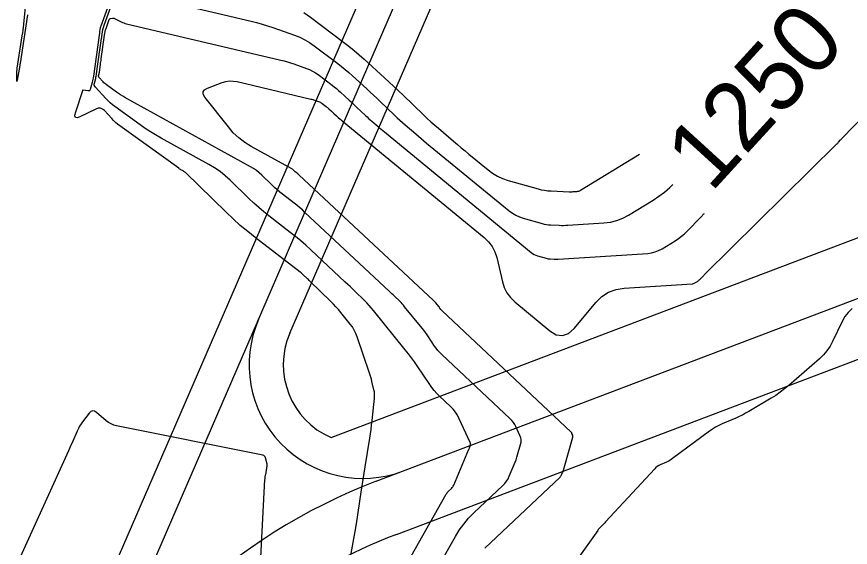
# Model space of a CAD drawing. Extents: x 658976 to 668726, y 639543 to 647196.
# Drawn here: x 661532.6 to 661605.9, y 641588.4 to 641635 of the extents above; entities that cross this region are included whole.
import ezdxf

# ---------------------------------------------------------------- set-up
doc = ezdxf.new("R2010")
doc.units = 0
for name, color, linetype in [('Ex_Contour Labels', 7, 'Continuous'), ('Ex_Major Contours', 7, 'Continuous'), ('Ex_Minor Contours', 7, 'Continuous'), ('R_Water', 7, 'Continuous')]:
    doc.layers.add(name, color=color, linetype=linetype)

msp = doc.modelspace()

# ---------------------------------------------------------------- linework, layer by layer
at = {"layer": 'Ex_Major Contours'}
for points in [[(661566.923, 641586.907), (661570.37, 641593.022), (661570.416, 641593.096), (661570.467, 641593.167), (661570.523, 641593.234), (661570.584, 641593.296), (661570.84, 641593.538), (661570.901, 641593.602), (661570.954, 641593.67), (661570.999, 641593.743), (661571.037, 641593.822), (661572.37, 641596.981), (661572.389, 641597.029), (661572.407, 641597.076), (661572.423, 641597.124), (661572.437, 641597.173), (661572.493, 641597.369), (661572.503, 641597.417), (661572.504, 641597.465), (661572.496, 641597.512), (661572.479, 641597.559), (661571.526, 641599.667), (661571.374, 641599.963), (661571.196, 641600.239), (661570.992, 641600.497), (661570.761, 641600.736), (661569.786, 641601.653), (661569.549, 641601.889), (661569.326, 641602.137), (661569.118, 641602.396), (661568.925, 641602.669), (661567.826, 641604.308), (661567.577, 641604.671), (661567.32, 641605.028), (661567.055, 641605.379), (661566.782, 641605.724), (661563.982, 641609.181), (661563.794, 641609.406), (661563.6, 641609.625), (661563.4, 641609.839), (661563.194, 641610.046), (661562.357, 641610.866), (661562.147, 641611.071), (661561.936, 641611.274), (661561.723, 641611.476), (661561.51, 641611.677), (661558.468, 641614.525), (661558.034, 641614.922), (661557.591, 641615.308), (661557.138, 641615.683), (661556.677, 641616.047), (661554.802, 641617.492), (661554.347, 641617.853), (661553.903, 641618.228), (661553.47, 641618.615), (661553.048, 641619.015), (661551.384, 641620.641), (661550.957, 641621.032), (661550.506, 641621.392), (661550.032, 641621.72), (661549.534, 641622.017), (661545.322, 641624.342), (661544.851, 641624.612), (661544.388, 641624.896), (661543.934, 641625.194), (661543.489, 641625.505), (661541.272, 641627.108), (661541.063, 641627.267), (661540.862, 641627.436), (661540.67, 641627.615), (661540.487, 641627.804), (661539.557, 641628.812), (661539.498, 641628.893), (661539.464, 641628.98), (661539.454, 641629.073), (661539.47, 641629.172), (661539.583, 641629.581), (661539.609, 641629.683), (661539.633, 641629.787), (661539.652, 641629.891), (661539.669, 641629.995), (661539.93, 641631.88), (661539.957, 641632.081), (661539.985, 641632.281), (661540.013, 641632.482), (661540.04, 641632.682), (661540.15, 641633.484), (661540.182, 641633.684), (661540.225, 641633.88), (661540.278, 641634.074), (661540.341, 641634.266), (661541.478, 641637.437)], [(661546.512, 641636.195), (661553.231, 641634.61), (661553.717, 641634.489), (661554.199, 641634.355), (661554.677, 641634.208), (661555.152, 641634.048), (661557.043, 641633.385), (661557.506, 641633.202), (661557.952, 641632.986), (661558.379, 641632.735), (661558.788, 641632.45), (661560.852, 641630.892), (661561.183, 641630.636), (661561.507, 641630.372), (661561.825, 641630.1), (661562.136, 641629.82), (661563.397, 641628.659), (661563.69, 641628.389), (661563.981, 641628.117), (661564.271, 641627.843), (661564.559, 641627.568), (661565.838, 641626.345), (661566.064, 641626.132), (661566.293, 641625.921), (661566.524, 641625.714), (661566.759, 641625.51), (661567.704, 641624.701), (661567.94, 641624.499), (661568.178, 641624.299), (661568.417, 641624.099), (661568.656, 641623.901), (661575.914, 641617.934), (661576.194, 641617.726), (661576.491, 641617.55), (661576.805, 641617.406), (661577.136, 641617.294), (661578.804, 641616.819), (661578.987, 641616.772), (661579.173, 641616.737), (661579.36, 641616.713), (661579.549, 641616.7), (661580.309, 641616.669), (661580.499, 641616.664), (661580.689, 641616.664), (661580.879, 641616.668), (661581.068, 641616.678), (661584.217, 641616.878), (661584.794, 641616.949), (661585.35, 641617.088), (661585.884, 641617.295), (661586.397, 641617.569), (661588.544, 641618.886), (661589.057, 641619.223), (661589.546, 641619.59), (661590.01, 641619.988), (661590.284, 641620.253)]]:
    msp.add_lwpolyline(points, dxfattribs=at)
at = {"layer": 'Ex_Minor Contours'}
for points in [[(661562.032, 641587.812), (661562.156, 641588.459), (661562.273, 641589.108), (661562.381, 641589.758), (661562.482, 641590.409), (661562.9, 641593.216), (661562.983, 641593.768), (661563.068, 641594.319), (661563.155, 641594.87), (661563.244, 641595.421), (661563.656, 641597.947), (661563.717, 641598.336), (661563.772, 641598.725), (661563.822, 641599.115), (661563.866, 641599.506), (661564.075, 641601.48), (661564.086, 641601.665), (661564.082, 641601.85), (661564.061, 641602.034), (661564.025, 641602.216), (661563.845, 641602.944), (661563.798, 641603.126), (661563.748, 641603.306), (661563.694, 641603.485), (661563.636, 641603.664), (661562.557, 641606.863), (661562.44, 641607.166), (661562.297, 641607.454), (661562.13, 641607.729), (661561.937, 641607.99), (661561.114, 641609.005), (661560.905, 641609.256), (661560.689, 641609.5), (661560.466, 641609.738), (661560.236, 641609.97), (661558.405, 641611.763), (661558.336, 641611.83), (661558.267, 641611.896), (661558.198, 641611.962), (661558.129, 641612.028), (661557.85, 641612.289), (661557.779, 641612.353), (661557.707, 641612.416), (661557.634, 641612.477), (661557.559, 641612.536), (661553.6, 641615.586), (661552.934, 641616.115), (661552.284, 641616.663), (661551.65, 641617.23), (661551.033, 641617.816), (661547.462, 641621.307), (661547.419, 641621.346), (661547.375, 641621.381), (661547.327, 641621.414), (661547.278, 641621.444), (661547.076, 641621.555), (661547.026, 641621.584), (661546.977, 641621.614), (661546.928, 641621.646), (661546.881, 641621.679), (661541.7, 641625.424), (661541.511, 641625.568), (661541.329, 641625.721), (661541.156, 641625.883), (661540.991, 641626.053), (661540.345, 641626.753), (661540.177, 641626.893), (661539.996, 641626.963), (661539.802, 641626.962), (661539.595, 641626.892), (661538.204, 641626.204), (661537.952, 641626.113), (661537.802, 641626.14), (661537.755, 641626.284), (661537.81, 641626.546), (661538.46, 641628.513), (661538.462, 641628.52), (661538.463, 641628.528), (661538.463, 641628.535), (661538.462, 641628.543), (661538.456, 641628.574), (661538.455, 641628.581), (661538.457, 641628.585), (661538.461, 641628.587), (661538.468, 641628.587), (661538.936, 641628.514), (661539.009, 641628.512), (661539.068, 641628.534), (661539.111, 641628.578), (661539.14, 641628.645), (661539.308, 641629.252), (661539.341, 641629.379), (661539.37, 641629.508), (661539.394, 641629.637), (661539.415, 641629.768), (661539.914, 641633.375), (661539.924, 641633.444), (661539.934, 641633.514), (661539.943, 641633.584), (661539.953, 641633.653), (661539.991, 641633.932), (661540.002, 641634.002), (661540.017, 641634.07), (661540.035, 641634.137), (661540.057, 641634.204), (661541.343, 641637.791)], [(661533.607, 641635.163), (661532.941, 641630.892), (661532.936, 641630.861), (661532.931, 641630.83), (661532.923, 641630.769), (661532.92, 641630.754), (661532.918, 641630.738), (661532.915, 641630.723), (661532.913, 641630.708), (661532.856, 641630.39), (661532.686, 641629.43), (661532.666, 641629.332), (661532.652, 641629.3), (661532.644, 641629.334), (661532.642, 641629.434), (661532.648, 641629.968), (661532.652, 641630.101), (661532.66, 641630.233), (661532.674, 641630.366), (661532.692, 641630.498), (661533.133, 641633.32), (661533.172, 641633.578), (661533.207, 641633.838), (661533.24, 641634.097), (661533.269, 641634.357), (661533.427, 641635.837)], [(661557.871, 641635.384), (661558.448, 641634.982), (661561.359, 641632.784), (661561.826, 641632.423), (661562.283, 641632.051), (661562.731, 641631.668), (661563.17, 641631.273), (661564.949, 641629.636), (661565.362, 641629.254), (661565.772, 641628.871), (661566.181, 641628.485), (661566.588, 641628.097), (661568.391, 641626.372), (661568.71, 641626.071), (661569.033, 641625.774), (661569.36, 641625.482), (661569.691, 641625.195), (661571.023, 641624.053), (661571.356, 641623.769), (661571.692, 641623.486), (661572.028, 641623.205), (661572.366, 641622.925), (661574.045, 641621.545), (661574.449, 641621.245), (661574.878, 641620.992), (661575.331, 641620.783), (661575.808, 641620.621), (661578.439, 641619.872), (661578.722, 641619.801), (661579.008, 641619.746), (661579.296, 641619.709), (661579.587, 641619.689), (661581.167, 641619.625), (661581.253, 641619.623), (661581.34, 641619.623), (661581.427, 641619.625), (661581.514, 641619.629), (661581.861, 641619.651), (661581.946, 641619.662), (661582.028, 641619.682), (661582.107, 641619.713), (661582.182, 641619.753), (661587.356, 641622.926)], [(661569.757, 641586.783), (661571.178, 641589.304), (661571.525, 641589.869), (661571.912, 641590.404), (661572.337, 641590.908), (661572.802, 641591.381), (661575.337, 641593.78), (661575.515, 641593.966), (661575.671, 641594.167), (661575.805, 641594.384), (661575.917, 641594.616), (661576.345, 641595.632), (661576.431, 641595.843), (661576.509, 641596.056), (661576.582, 641596.271), (661576.647, 641596.489), (661576.905, 641597.389), (661576.945, 641597.593), (661576.949, 641597.795), (661576.916, 641597.995), (661576.846, 641598.191), (661576.493, 641598.972), (661576.396, 641599.162), (661576.282, 641599.339), (661576.151, 641599.504), (661576.004, 641599.657), (661569.977, 641605.322), (661569.807, 641605.491), (661569.647, 641605.669), (661569.498, 641605.856), (661569.359, 641606.051), (661568.823, 641606.85), (661568.687, 641607.048), (661568.547, 641607.243), (661568.402, 641607.435), (661568.253, 641607.624), (661566.724, 641609.512), (661566.621, 641609.634), (661566.516, 641609.754), (661566.406, 641609.871), (661566.294, 641609.984), (661565.836, 641610.432), (661565.722, 641610.544), (661565.607, 641610.655), (661565.491, 641610.765), (661565.374, 641610.875), (661557.968, 641617.808), (661557.736, 641618.02), (661557.498, 641618.227), (661557.256, 641618.428), (661557.008, 641618.624), (661556.003, 641619.398), (661555.759, 641619.591), (661555.521, 641619.792), (661555.289, 641620), (661555.063, 641620.214), (661554.172, 641621.086), (661553.942, 641621.295), (661553.701, 641621.488), (661553.447, 641621.664), (661553.18, 641621.823), (661542.141, 641627.918), (661541.955, 641628.024), (661541.773, 641628.136), (661541.594, 641628.254), (661541.418, 641628.377), (661540.544, 641629.008), (661540.462, 641629.071), (661540.383, 641629.138), (661540.307, 641629.209), (661540.235, 641629.283), (661539.868, 641629.68), (661539.845, 641629.712), (661539.831, 641629.747), (661539.827, 641629.783), (661539.834, 641629.822), (661539.878, 641629.984), (661539.889, 641630.024), (661539.898, 641630.065), (661539.906, 641630.106), (661539.912, 641630.147), (661540.003, 641630.802), (661540.02, 641630.925), (661540.037, 641631.048), (661540.054, 641631.171), (661540.071, 641631.295), (661540.358, 641633.397), (661540.382, 641633.547), (661540.415, 641633.695), (661540.455, 641633.841), (661540.502, 641633.986), (661540.781, 641634.763), (661540.799, 641634.8), (661540.825, 641634.829), (661540.858, 641634.848), (661540.898, 641634.859), (661541.072, 641634.886), (661541.115, 641634.889), (661541.157, 641634.886), (661541.198, 641634.876), (661541.238, 641634.859), (661541.826, 641634.561), (661541.938, 641634.508), (661542.053, 641634.462), (661542.17, 641634.423), (661542.29, 641634.391), (661555.851, 641631.192), (661556.137, 641631.12), (661556.422, 641631.041), (661556.704, 641630.955), (661556.983, 641630.861), (661558.098, 641630.469), (661558.372, 641630.362), (661558.634, 641630.234), (661558.886, 641630.086), (661559.127, 641629.918), (661560.344, 641628.999), (661560.54, 641628.848), (661560.731, 641628.692), (661560.918, 641628.532), (661561.102, 641628.367), (661561.845, 641627.683), (661562.018, 641627.523), (661562.19, 641627.363), (661562.36, 641627.202), (661562.531, 641627.039), (661563.284, 641626.318), (661563.418, 641626.192), (661563.553, 641626.068), (661563.689, 641625.946), (661563.828, 641625.826), (661564.385, 641625.349), (661564.524, 641625.23), (661564.664, 641625.111), (661564.805, 641624.994), (661564.946, 641624.877), (661577.835, 641614.28), (661577.964, 641614.184), (661578.101, 641614.103), (661578.246, 641614.037), (661578.399, 641613.985), (661579.168, 641613.766), (661579.253, 641613.744), (661579.338, 641613.728), (661579.425, 641613.717), (661579.512, 641613.711), (661579.862, 641613.697), (661579.95, 641613.694), (661580.037, 641613.694), (661580.125, 641613.696), (661580.212, 641613.701), (661588.071, 641614.2), (661588.405, 641614.241), (661588.727, 641614.322), (661589.036, 641614.441), (661589.333, 641614.6), (661590.497, 641615.314), (661590.781, 641615.5), (661591.051, 641615.704), (661591.309, 641615.924), (661591.552, 641616.161), (661592.732, 641617.381), (661593.009, 641617.665), (661593.061, 641617.718)], [(661573.762, 641588.278), (661580.379, 641594.538), (661580.418, 641594.578), (661580.451, 641594.621), (661580.48, 641594.668), (661580.504, 641594.718), (661580.591, 641594.924), (661580.612, 641594.976), (661580.632, 641595.029), (661580.65, 641595.082), (661580.666, 641595.135), (661581.501, 641598.053), (661581.509, 641598.094), (661581.509, 641598.134), (661581.503, 641598.174), (661581.489, 641598.214), (661581.418, 641598.37), (661581.398, 641598.408), (661581.376, 641598.444), (661581.349, 641598.477), (661581.32, 641598.508), (661570.015, 641609.135), (661569.986, 641609.164), (661569.959, 641609.194), (661569.934, 641609.225), (661569.911, 641609.258), (661569.82, 641609.393), (661569.797, 641609.426), (661569.774, 641609.459), (661569.749, 641609.492), (661569.724, 641609.523), (661569.466, 641609.842), (661569.449, 641609.863), (661569.431, 641609.883), (661569.412, 641609.903), (661569.393, 641609.922), (661569.316, 641609.997), (661569.297, 641610.016), (661569.277, 641610.035), (661569.258, 641610.054), (661569.238, 641610.072), (661557.468, 641621.09), (661557.437, 641621.119), (661557.405, 641621.147), (661557.373, 641621.174), (661557.34, 641621.2), (661557.205, 641621.304), (661557.172, 641621.33), (661557.14, 641621.357), (661557.109, 641621.384), (661557.079, 641621.413), (661556.959, 641621.53), (661556.928, 641621.558), (661556.896, 641621.584), (661556.862, 641621.608), (661556.826, 641621.629), (661553.24, 641623.609), (661552.674, 641623.959), (661552.151, 641624.36), (661551.671, 641624.812), (661551.235, 641625.315), (661549.174, 641627.942), (661549.028, 641628.195), (661549.016, 641628.41), (661549.138, 641628.588), (661549.394, 641628.728), (661550.684, 641629.215), (661551.008, 641629.311), (661551.335, 641629.358), (661551.666, 641629.354), (661552, 641629.3), (661558.47, 641627.773), (661558.558, 641627.752), (661558.644, 641627.728), (661558.73, 641627.701), (661558.815, 641627.673), (661559.154, 641627.554), (661559.237, 641627.521), (661559.317, 641627.482), (661559.393, 641627.437), (661559.467, 641627.386), (661559.837, 641627.107), (661559.896, 641627.061), (661559.954, 641627.013), (661560.011, 641626.965), (661560.067, 641626.914), (661560.293, 641626.706), (661560.346, 641626.658), (661560.398, 641626.609), (661560.45, 641626.56), (661560.502, 641626.511), (661560.731, 641626.291), (661560.772, 641626.253), (661560.813, 641626.215), (661560.854, 641626.178), (661560.896, 641626.142), (661561.066, 641625.996), (661561.108, 641625.96), (661561.151, 641625.924), (661561.193, 641625.889), (661561.236, 641625.853), (661573.71, 641615.597), (661574.096, 641615.226), (661574.407, 641614.809), (661574.644, 641614.345), (661574.806, 641613.835), (661575.305, 641611.703), (661575.467, 641611.193), (661575.704, 641610.729), (661576.014, 641610.311), (661576.399, 641609.939), (661579.477, 641607.396), (661580.045, 641607.049), (661580.589, 641606.966), (661581.109, 641607.146), (661581.604, 641607.591), (661583.539, 641609.898), (661584.056, 641610.408), (661584.64, 641610.786), (661585.291, 641611.033), (661586.009, 641611.146), (661591.978, 641611.526), (661592.043, 641611.534), (661592.106, 641611.549), (661592.166, 641611.573), (661592.223, 641611.603), (661592.449, 641611.742), (661592.504, 641611.778), (661592.557, 641611.818), (661592.607, 641611.861), (661592.654, 641611.907), (661592.883, 641612.143), (661592.937, 641612.199), (661592.991, 641612.253), (661593.045, 641612.308), (661593.1, 641612.362), (661604.668, 641623.792), (661604.713, 641623.838), (661604.758, 641623.884), (661604.801, 641623.932), (661604.844, 641623.98), (661605.011, 641624.174), (661605.054, 641624.223), (661605.097, 641624.27), (661605.141, 641624.317), (661605.185, 641624.364), (661609.909, 641629.215)], [(661606.022, 641609.347), (661605.687, 641609.016), (661605.401, 641608.641), (661605.165, 641608.222), (661604.319, 641606.461), (661604.088, 641606.035), (661603.818, 641605.64), (661603.509, 641605.274), (661603.161, 641604.937), (661600.474, 641602.591), (661600.102, 641602.28), (661599.716, 641601.988), (661599.318, 641601.713), (661598.906, 641601.456), (661596.955, 641600.301), (661596.674, 641600.14), (661596.388, 641599.989), (661596.098, 641599.847), (661595.803, 641599.714), (661594.612, 641599.201), (661594.32, 641599.065), (661594.036, 641598.912), (661593.762, 641598.743), (661593.497, 641598.558), (661590.261, 641596.155), (661590.136, 641596.067), (661590.007, 641595.988), (661589.873, 641595.916), (661589.735, 641595.852), (661589.174, 641595.611), (661589.038, 641595.544), (661588.911, 641595.464), (661588.794, 641595.371), (661588.686, 641595.266), (661584.357, 641590.582), (661584.3, 641590.521), (661584.243, 641590.46), (661584.185, 641590.4), (661584.127, 641590.34), (661583.893, 641590.102), (661583.836, 641590.041), (661583.781, 641589.978), (661583.729, 641589.914), (661583.679, 641589.847), (661580.182, 641584.925)], [(661553.985, 641585.164), (661554.454, 641594.321), (661554.458, 641594.378), (661554.464, 641594.434), (661554.472, 641594.49), (661554.482, 641594.546), (661554.533, 641594.804), (661554.54, 641594.841), (661554.547, 641594.879), (661554.553, 641594.917), (661554.559, 641594.955), (661554.584, 641595.119), (661554.588, 641595.151), (661554.593, 641595.183), (661554.598, 641595.216), (661554.604, 641595.248), (661554.628, 641595.395), (661554.631, 641595.418), (661554.635, 641595.441), (661554.637, 641595.463), (661554.64, 641595.486), (661554.65, 641595.578), (661554.651, 641595.6), (661554.651, 641595.623), (661554.648, 641595.645), (661554.644, 641595.668), (661554.51, 641596.21), (661554.476, 641596.298), (661554.424, 641596.367), (661554.353, 641596.416), (661554.264, 641596.446), (661541.421, 641599.036), (661541.169, 641599.103), (661540.932, 641599.201), (661540.709, 641599.329), (661540.502, 641599.487), (661539.66, 641600.215), (661539.485, 641600.327), (661539.319, 641600.354), (661539.162, 641600.294), (661539.013, 641600.148), (661538.437, 641599.392), (661538.299, 641599.199), (661538.174, 641598.999), (661538.06, 641598.792), (661537.958, 641598.578), (661537.574, 641597.702), (661537.478, 641597.484), (661537.381, 641597.266), (661537.283, 641597.048), (661537.185, 641596.831), (661533.38, 641588.459), (661532.957, 641587.491)]]:
    msp.add_lwpolyline(points, dxfattribs=at)
at = {"layer": 'R_Water'}
for p, q in [((661564.222, 641594.16), (662140.694, 641813.249)), ((661540.522, 641585.062), (661636.891, 641807.824)), ((661536.096, 641567.274), (661639.645, 641806.633)), ((661556.634, 641607.195), (661642.398, 641805.442)), ((661560.256, 641598.001), (661640.156, 641628.367)), ((661565.999, 641589.486), (661638.217, 641616.933))]:
    msp.add_line(p, q, dxfattribs=at)
for centre, radius, start, end in [((661563.059, 641604.415), 10, 156.60619, 290.80943), ((661563.059, 641604.415), 7, 156.60619, 246.39412), ((661581.985, 641547.421), 50, 110.80943, 156.60619), ((661581.985, 641547.421), 45, 110.80943, 144.5047)]:
    msp.add_arc(centre, radius, start, end, dxfattribs=at)

# ---------------------------------------------------------------- texts
at = {"layer": 'Ex_Contour Labels'}
msp.add_text('1250', height=6, rotation=47.61073, dxfattribs=at).set_placement((661593.624, 641619.462))

doc.saveas('drawing.dxf')
